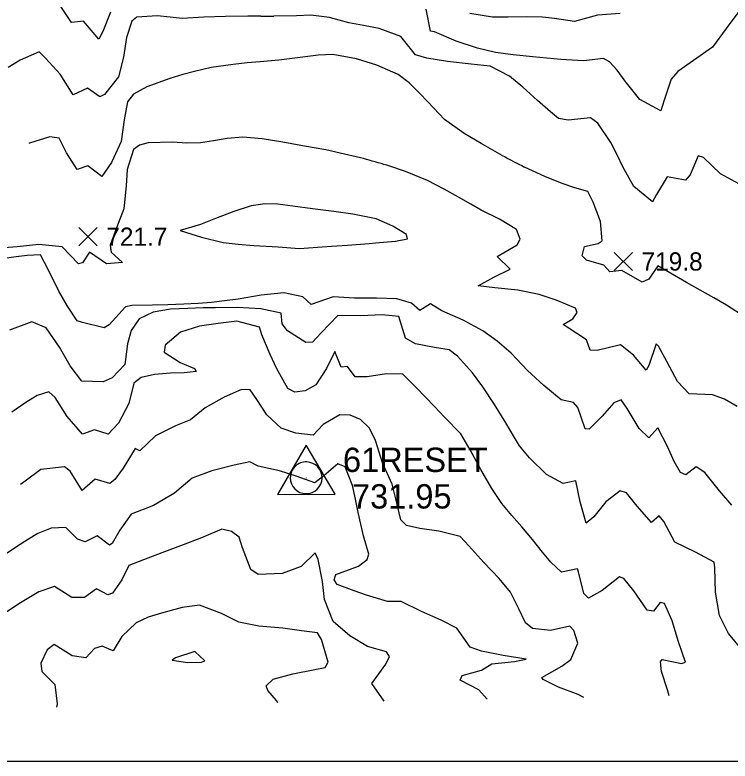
# Model space of a CAD drawing. Extents: x 2566079 to 2571326, y 424054 to 426896.
# Drawn here: x 2568149 to 2568737, y 424077 to 424690 of the extents above; entities that cross this region are included whole.
import ezdxf

# ---------------------------------------------------------------- set-up
doc = ezdxf.new("R2010")
doc.units = 0
for name, color, linetype in [('Contour_ADS_Major', 7, 'Continuous'), ('Contour_ADS_Minor', 7, 'Continuous'), ('Contour_ADS_Spot_Elevation', 7, 'Continuous'), ('Contour_ADS_State_Plane_Border', 7, 'Continuous'), ('Control_Point', 7, 'Continuous')]:
    doc.layers.add(name, color=color, linetype=linetype)

# ---------------------------------------------------------------- blocks, each defined once
blk = doc.blocks.new('S750')
at = {"layer": 'Contour_ADS_Spot_Elevation'}
for p, q in [((-0.5, 0.498), (0.5, -0.498)), ((-0.498, -0.5), (0.498, 0.5))]:
    blk.add_line(p, q, dxfattribs=at)
blk = doc.blocks.new('S803')
at = {"layer": 'Control_Point'}
for q in [(0, 0.002), (0, 0), (0, 0), (0, 0)]:
    blk.add_line((0, 0), q, dxfattribs=at)
blk.add_lwpolyline([(-0.007, 0.677), (-0.597, -0.336), (-0.597, -0.336), (0.587, -0.332), (-0.007, 0.677)], dxfattribs=at)
for centre, radius, start, end in [((-0.005, 0.005), 0.327, 88.1387, 179.8395), ((-0.005, 0.006), 0.326, 269.4188, 88.1799), ((-0.007, 0.005), 0.325, 179.8295, 269.8262)]:
    blk.add_arc(centre, radius, start, end, dxfattribs=at)

msp = doc.modelspace()

# ---------------------------------------------------------------- linework, layer by layer
at = {"layer": 'Contour_ADS_Major'}
for points in [[(2568549.85, 424574.7), (2568532.41, 424584.45), (2568518.5, 424592.66), (2568502.34, 424604.36), (2568488.92, 424618.43), (2568481.63, 424626.16), (2568473.24, 424634.28), (2568464.37, 424641.21), (2568446.92, 424648.81), (2568430.12, 424654), (2568410.76, 424657.7), (2568398.56, 424657.18), (2568385.96, 424655.57), (2568366.39, 424652.86), (2568350.92, 424651.71), (2568340.3, 424650.76), (2568328.74, 424649.55), (2568310.73, 424647.08), (2568297.07, 424643.77), (2568287.47, 424641.09), (2568276.62, 424637.89), (2568257.79, 424631.16), (2568246.75, 424625.15), (2568241.8, 424618.62), (2568239.23, 424604.06), (2568236.83, 424586.07), (2568228.74, 424569.03), (2568220.9, 424557.49), (2568209.37, 424566.13), (2568200.71, 424563.14), (2568191.95, 424576.74), (2568185.68, 424588.91), (2568178.12, 424589.96), (2568161.52, 424584.69), (2568160.91, 424584.43)], [(2568750.24, 424441.21), (2568733.97, 424451.64), (2568723.72, 424457.62), (2568712.4, 424464.13), (2568701.36, 424470.45), (2568686.1, 424479.17), (2568677.62, 424484.07), (2568670.19, 424472.92), (2568664.82, 424470.49), (2568648.2, 424480.12), (2568638.26, 424479.05), (2568633.27, 424484.58), (2568619.12, 424488.7), (2568615.49, 424492.12), (2568617.31, 424499.79), (2568628.71, 424502.41), (2568631.96, 424504.62), (2568630.64, 424520.37), (2568624.62, 424536.32), (2568620.03, 424545.13), (2568609.35, 424548.08), (2568599, 424551.67), (2568584.96, 424557.39), (2568568.16, 424565.18)], [(2568616.82, 424129.4), (2568612.14, 424131.83), (2568596.16, 424137.89), (2568583.52, 424144), (2568582.28, 424145.8), (2568598.74, 424155.21), (2568606.07, 424160.44), (2568612.07, 424173.95), (2568608.68, 424184.45), (2568605.37, 424187.94), (2568589.39, 424184.5), (2568574.82, 424186.09), (2568569.03, 424190.67), (2568563.29, 424202.87), (2568556.49, 424215.77), (2568547.3, 424227.25), (2568534.67, 424240.38), (2568522.25, 424253.84), (2568515.21, 424261.69), (2568497.65, 424266), (2568482.26, 424268.1), (2568471.13, 424270.79), (2568466.52, 424275.36), (2568462.34, 424292.62), (2568459.46, 424304.62), (2568451.37, 424322.26), (2568445.81, 424340.46), (2568440.66, 424350.57), (2568433.37, 424357.72), (2568424.85, 424361.35), (2568416.31, 424361.46), (2568402.82, 424353.62), (2568394.43, 424344.91), (2568380.2, 424346.53), (2568368.26, 424350.55), (2568356.5, 424361.72), (2568348.12, 424374.22), (2568342.62, 424382.08), (2568335.56, 424382.48), (2568321.49, 424376.07), (2568305.75, 424367.22), (2568293.75, 424357.61), (2568281.4, 424352.59), (2568264.93, 424344.41), (2568252, 424331.89), (2568248.18, 424333.83), (2568238.4, 424317.68), (2568231.45, 424308.42), (2568227.38, 424305.11), (2568215.45, 424308.8), (2568204.68, 424299.52), (2568194.83, 424315.18), (2568190.26, 424318.82), (2568170.71, 424316.66), (2568157.85, 424307.01), (2568153.92, 424304.34)]]:
    msp.add_lwpolyline(points, dxfattribs=at)
msp.add_arc((2568812.9, 425058.27), 550.49, 241.45449, 243.60256, dxfattribs=at)
at = {"layer": 'Contour_ADS_Minor'}
for points in [[(2568228.07, 424692.54), (2568221.78, 424676.61), (2568218.51, 424670.3), (2568205.88, 424685.08), (2568195.84, 424683.95), (2568184.98, 424700.31)], [(2568745.04, 424694.1), (2568733.81, 424678.88), (2568722.68, 424663.56), (2568707.04, 424652.77), (2568694.22, 424643.67), (2568688.67, 424637.46), (2568682.95, 424620.04), (2568680.15, 424611.3), (2568662.76, 424620.74), (2568650.7, 424635.71), (2568644.25, 424644.68), (2568638.09, 424651.63), (2568633.03, 424654.4), (2568616.52, 424652.46), (2568598.02, 424653.55), (2568586.41, 424654.62), (2568574.84, 424655.75), (2568558.83, 424657.39), (2568544.29, 424659.29), (2568529.56, 424662.96), (2568512.05, 424668.7), (2568494.25, 424676.22), (2568490.8, 424676.94), (2568487.28, 424694.85)], [(2568646.81, 424691.3), (2568628.19, 424689.96), (2568609.12, 424684.85), (2568592.67, 424687.34), (2568582.88, 424688.32), (2568569.38, 424688.58), (2568554.65, 424688.44), (2568541.83, 424688.36), (2568523.23, 424691.2)], [(2568340.93, 424689.03), (2568322.36, 424688.82), (2568304.72, 424688.24), (2568286.86, 424687.16), (2568277.1, 424688.23), (2568266.19, 424689.39), (2568249.72, 424688.38), (2568245.54, 424685.02), (2568241.12, 424671.52), (2568238.58, 424655.57), (2568234.48, 424639.31), (2568223.08, 424624.87), (2568219.15, 424622.89), (2568209.16, 424630.01), (2568197.33, 424624.54), (2568186.72, 424641.39), (2568174.48, 424654.71), (2568169.3, 424659.72), (2568153.66, 424652.92), (2568143.78, 424646.86)], [(2568744.23, 424551.31), (2568729.27, 424559.69), (2568715.11, 424572.97), (2568710.74, 424574.29), (2568704.2, 424558.89), (2568700.45, 424554.29), (2568685.41, 424557.15), (2568676.44, 424542.58), (2568673.2, 424536.62), (2568658.05, 424549.06), (2568648.94, 424565.23), (2568644.2, 424575.08), (2568639.07, 424585.25), (2568628.39, 424601.35), (2568622.41, 424605.51), (2568604.03, 424603.64), (2568595.99, 424605.13), (2568589.38, 424610.54), (2568578.9, 424619.86), (2568566.69, 424630.71), (2568555.72, 424639.96), (2568539.87, 424648.14), (2568524.39, 424649.8), (2568504.92, 424651.98), (2568487.96, 424654.5), (2568478.69, 424657.46), (2568466.4, 424672.52), (2568448.78, 424679.03), (2568435.96, 424681.43), (2568423.85, 424683.66), (2568407.94, 424687.96), (2568392.5, 424689.86), (2568380.87, 424689.53), (2568362.3, 424689.25)], [(2568433.34, 424572.69), (2568416.77, 424576.7), (2568404.87, 424579.22), (2568395.2, 424580.99), (2568384.22, 424582.96), (2568369.46, 424585.72), (2568352.68, 424588.37), (2568336.73, 424589.63), (2568323.69, 424588.71), (2568312.67, 424586.66), (2568302.05, 424585), (2568290.63, 424584.83), (2568279, 424585.49), (2568259.03, 424585.17), (2568251.85, 424583.11), (2568246.76, 424579.71), (2568241.68, 424563.04), (2568240.97, 424549.71), (2568238.85, 424530.85), (2568233.02, 424515.28), (2568227.66, 424500.96), (2568228.48, 424495.31), (2568237.81, 424486.66), (2568224.7, 424485.62), (2568210.58, 424495.22), (2568204.95, 424486.6), (2568201.63, 424485.58), (2568188.37, 424499.65), (2568169.21, 424501.64), (2568151.31, 424499.51), (2568133.44, 424498.22)], [(2568742.83, 424368.33), (2568732.46, 424374.33), (2568722.54, 424378.13), (2568703.28, 424378.8), (2568693.74, 424389.05), (2568685.08, 424405.49), (2568678.32, 424418.09), (2568676.19, 424419.87), (2568670.25, 424402.25), (2568668.12, 424398.36), (2568657.68, 424410.62), (2568647, 424419.2), (2568627.71, 424414.47), (2568622.13, 424414.67), (2568618.98, 424423.08), (2568603.13, 424433.59), (2568599.83, 424435.92), (2568607.8, 424440.36), (2568611.42, 424445.77), (2568610.14, 424449.28), (2568594.15, 424455.8), (2568580.04, 424460.38), (2568562.51, 424463.9), (2568543.79, 424466.04), (2568530.09, 424467.65), (2568542.96, 424474.64), (2568556.22, 424481.17), (2568545.55, 424491.56), (2568562, 424501.17), (2568564.64, 424505.87), (2568561.64, 424513.78), (2568547.5, 424522.45), (2568532.65, 424529.8), (2568523.93, 424534.65), (2568513.91, 424540.4), (2568502.21, 424547.01), (2568488.35, 424554.05), (2568471.81, 424560.99)], [(2568738.35, 424287.36), (2568728.28, 424299.26), (2568716.25, 424314.2), (2568709.05, 424318.94), (2568700.57, 424312.37), (2568696.27, 424314.24), (2568691.03, 424323.19), (2568685.57, 424335.56), (2568677.55, 424350.85), (2568670.4, 424342.7), (2568662.38, 424350.43), (2568652.34, 424366.87), (2568647.51, 424373.94), (2568641.46, 424371.47), (2568631.98, 424360.61), (2568621.15, 424349.74), (2568618.03, 424349.96), (2568611.93, 424367.59), (2568608.51, 424371.66), (2568598.25, 424373.92), (2568584.04, 424385.66), (2568570.51, 424397.9), (2568557.03, 424412.15), (2568545.54, 424422), (2568533.76, 424430.68), (2568517.69, 424439.42), (2568500.26, 424447.09), (2568490.93, 424452.92), (2568482.17, 424447.41), (2568475.34, 424453.26), (2568463.18, 424456.88), (2568446.59, 424457.35), (2568428.46, 424457.57), (2568410.92, 424458.6), (2568392.88, 424452.24), (2568386.1, 424458.55), (2568370.38, 424461.73), (2568351.81, 424459.79), (2568332.9, 424456.72), (2568321.65, 424455.12), (2568310.82, 424453.92), (2568299.96, 424453.09), (2568288.2, 424452.51), (2568275.18, 424452.07), (2568262.45, 424451.74), (2568245.44, 424451.33), (2568240.34, 424450.34), (2568226.99, 424435.62), (2568222.72, 424432.94), (2568204.97, 424437.51), (2568200.54, 424438.81), (2568192.59, 424450.87), (2568185.5, 424463.12), (2568177.05, 424480.55), (2568170.48, 424492.92), (2568159.43, 424492.49), (2568150.52, 424491.51), (2568138.3, 424489.86)], [(2568746.2, 424169.44), (2568735.8, 424182), (2568728.38, 424196.68), (2568725.02, 424215.85), (2568724.58, 424235.78), (2568724.08, 424240.61), (2568708.55, 424248.88), (2568691.55, 424256.84), (2568682.72, 424273.85), (2568678.78, 424278.58), (2568672.44, 424273.13), (2568660.64, 424286.49), (2568651.88, 424297.56), (2568646.68, 424299.17), (2568635.07, 424290.14), (2568625.05, 424277.82), (2568618.84, 424272.66), (2568613.74, 424289.99), (2568610.24, 424307.41), (2568599.79, 424305.12), (2568586.27, 424312.48), (2568572.33, 424326.24), (2568564.02, 424336.11), (2568559.94, 424342.93), (2568552.74, 424355.04), (2568543.56, 424370.04), (2568533.99, 424384.62), (2568525.4, 424396.1), (2568512.99, 424409.84), (2568506.11, 424414.96), (2568494.23, 424417.01), (2568478.43, 424419.9), (2568470.42, 424424.68), (2568464.81, 424442.41), (2568451.17, 424443.84), (2568433.75, 424442.93), (2568414.79, 424443.25), (2568401.09, 424428.88), (2568393.89, 424421.34), (2568388.53, 424420.96), (2568373.43, 424430.68), (2568369.03, 424436.48), (2568368.31, 424445.01), (2568351.59, 424448.6), (2568332.21, 424449.79), (2568314.1, 424449.61), (2568304.13, 424449.38), (2568291.6, 424449.05), (2568277.17, 424448.34), (2568263, 424445.98), (2568251.62, 424440.41), (2568244.88, 424430.89), (2568241.8, 424419.84), (2568239.83, 424403.02), (2568229.32, 424391.95), (2568221.84, 424388.62), (2568204.48, 424389.3), (2568194.74, 424401.9), (2568186.04, 424417.09), (2568175.2, 424433.18), (2568163.46, 424438), (2568144.99, 424431.12)], [(2568686.86, 424130.67), (2568685.56, 424135.6), (2568680.76, 424150.6), (2568679.76, 424158.65), (2568681.3, 424160.55), (2568697.05, 424157.3), (2568700.35, 424158.29), (2568694.64, 424175.08), (2568689.36, 424192.24), (2568683.09, 424206.53), (2568679.64, 424207.47), (2568674.1, 424200.15), (2568668.82, 424201.14), (2568657.85, 424217.12), (2568649.7, 424227.19), (2568646.07, 424228.43), (2568632.06, 424217.25), (2568620.68, 424210.99), (2568616.88, 424214.89), (2568612.36, 424232.6), (2568611.79, 424235.07), (2568598.41, 424232.32), (2568589.82, 424240.62), (2568583.03, 424248.88), (2568574.64, 424259.08), (2568565.85, 424269.48), (2568557.58, 424278.93), (2568549.56, 424288.78), (2568541.18, 424300.99), (2568532.16, 424316.58), (2568523.35, 424332.78), (2568515.92, 424345.9), (2568502.36, 424359.66), (2568494.13, 424368.42), (2568486.8, 424376.07), (2568478.75, 424384.35), (2568468.15, 424395.09), (2568454.85, 424395.18), (2568438.9, 424392.9), (2568428.97, 424392.88), (2568422.76, 424401.29), (2568417.53, 424400.66), (2568412.41, 424413.71), (2568405.57, 424399.57), (2568396.6, 424386.13), (2568387.92, 424381.33), (2568379.34, 424380.08), (2568373.55, 424383.19), (2568364.75, 424399.38), (2568359.16, 424411.17), (2568352.19, 424427.24), (2568350.44, 424433.65), (2568331.86, 424438.58), (2568316.47, 424436.59), (2568301.06, 424434.42), (2568285.45, 424429.52), (2568272.9, 424418.75), (2568272.19, 424413.01), (2568285.22, 424404.6), (2568297.03, 424399.67), (2568298.48, 424397.12), (2568288.38, 424395.98), (2568277.21, 424395.76), (2568264.24, 424394.79), (2568253.27, 424392.22), (2568247.07, 424387.57), (2568243.07, 424370.82), (2568234.56, 424354.79), (2568226.17, 424345.83), (2568214.91, 424349.34), (2568204.9, 424345.58), (2568192.44, 424360.21), (2568182.39, 424375.94), (2568177.29, 424380.49), (2568167.68, 424377.51), (2568158.45, 424371.71), (2568146.92, 424363.66)], [(2568537.52, 424127.96), (2568530.61, 424135.54), (2568515.23, 424143.67), (2568516.97, 424147.39), (2568532.78, 424151.68), (2568541.27, 424157.03), (2568559.88, 424158.96), (2568569.42, 424160.97), (2568550.52, 424163.86), (2568532.77, 424167.29), (2568523.56, 424170.78), (2568512.5, 424186.34), (2568499.59, 424192.76), (2568483.47, 424199.91), (2568466.91, 424208.33), (2568455.62, 424208.19), (2568438.42, 424213.51), (2568428.12, 424216.87), (2568414.2, 424222.31), (2568411.74, 424225.96), (2568413.02, 424230.44), (2568431.75, 424237.16), (2568438.83, 424242.68), (2568440.26, 424247.12), (2568435.92, 424262.1), (2568431.54, 424281.48), (2568429.3, 424292.32), (2568426.75, 424303.65), (2568420.86, 424318.78), (2568414.84, 424321.44), (2568403.14, 424311.48), (2568395.97, 424305.83), (2568380.58, 424311.29), (2568366.74, 424315.48), (2568349.21, 424319.38), (2568342.51, 424323.03), (2568329.57, 424320.16), (2568311.28, 424315.61), (2568295.06, 424309.51), (2568280.58, 424297.13), (2568263.41, 424287.21), (2568244.84, 424279.9), (2568235.63, 424266.85), (2568229.31, 424255.84), (2568227.18, 424254.58), (2568216.88, 424262.27), (2568207.13, 424257.34), (2568200.76, 424259.33), (2568191.32, 424268.89), (2568179.18, 424268.46), (2568168.19, 424264.08), (2568160.53, 424259.51), (2568150.8, 424253.19), (2568138.92, 424245.29)], [(2568452.71, 424126.42), (2568442.79, 424140.98), (2568454.28, 424156.64), (2568457.17, 424163.13), (2568454.76, 424166.86), (2568439.02, 424171.29), (2568424.5, 424179.97), (2568410.83, 424191.77), (2568403.74, 424209.82), (2568402.17, 424224.69), (2568398.57, 424242.73), (2568396.11, 424248.15), (2568384.63, 424237.01), (2568368.98, 424231.22), (2568349.19, 424230.46), (2568343.35, 424234.53), (2568336.37, 424252.34), (2568333.67, 424260.97), (2568327.5, 424265.76), (2568319.54, 424267.67), (2568302.7, 424260.6), (2568287.63, 424254.84), (2568270.06, 424248.14), (2568255.15, 424242.47), (2568243.03, 424237.69), (2568237.16, 424226.07), (2568229.49, 424215.14), (2568225.74, 424213.67), (2568216.51, 424218.54), (2568206.55, 424211.55), (2568196.17, 424211.42), (2568182, 424220.62), (2568169.15, 424216.11), (2568152.61, 424206.25), (2568141.59, 424198.81)], [(2568365.57, 424124.83), (2568364.34, 424126.83), (2568357.31, 424135.05), (2568355.79, 424138.82), (2568361.52, 424144.35), (2568377.88, 424148.8), (2568395.72, 424152.35), (2568404.26, 424154.12), (2568406.94, 424158.37), (2568401.26, 424176.89), (2568398.18, 424182.48), (2568384.98, 424184.12), (2568369.58, 424186.19), (2568349.74, 424188.06), (2568333.51, 424191.16), (2568319.25, 424198.42), (2568301.06, 424205.17), (2568286.72, 424203.37), (2568269.79, 424198.74), (2568258.86, 424195.28), (2568248.98, 424190.8), (2568237.15, 424179.49), (2568230.11, 424167.72), (2568221.01, 424171.65), (2568214.7, 424169.74), (2568207.78, 424161.92), (2568196.57, 424163.52), (2568181.67, 424172.91), (2568175.92, 424168.57), (2568170.78, 424157.55), (2568171.59, 424150.81), (2568182.12, 424140.08), (2568184.02, 424124.09), (2568183.48, 424121.52)]]:
    msp.add_lwpolyline(points, dxfattribs=at)
for points in [[(2568445.63, 424502.78), (2568462.22, 424504.33), (2568471.86, 424506.06), (2568471.17, 424509.68), (2568459.95, 424516.73), (2568446.28, 424522.74), (2568427.17, 424526.56), (2568411.49, 424528.69), (2568393.87, 424530.95), (2568377.72, 424533.09), (2568365.43, 424534.74), (2568355.07, 424535.08), (2568343.65, 424533.21), (2568329.25, 424528.68), (2568314.18, 424522.96), (2568301.86, 424517.99), (2568285.26, 424513.02), (2568302.61, 424507.68), (2568320.41, 424503.2), (2568332.83, 424501.71), (2568345.83, 424500.76), (2568365.7, 424499.57), (2568383.27, 424498.16), (2568397.93, 424499.3), (2568409.54, 424500.16), (2568422.61, 424501.1), (2568440.51, 424502.35), (2568445.63, 424502.78)], [(2568291.24, 424157.98), (2568302.86, 424158.31), (2568305.56, 424159.42), (2568297.14, 424167.02), (2568281.31, 424161.98), (2568278.61, 424159.97), (2568291.24, 424157.98)]]:
    msp.add_lwpolyline(points, close=True, dxfattribs=at)
for centre, radius, start, end in [((2568566.27, 403309.09), 21381.13, 90.575228, 90.603875), ((2568316.04, 428662.41), 3973.43, 270.5131, 270.66711), ((2568313.29, 424101.96), 485.8, 73.32594, 75.69308), ((2568360.23, 424256.34), 324.44, 69.88414, 73.44375)]:
    msp.add_arc(centre, radius, start, end, dxfattribs=at)
at = {"layer": 'Contour_ADS_State_Plane_Border'}
msp.add_lwpolyline([(2566079.33, 424077.11), (2571302.93, 424077.11), (2571302.93, 426873.74), (2566079.33, 426873.74), (2566079.33, 424077.11)], close=True, dxfattribs=at)

# ---------------------------------------------------------------- block references
at = {"layer": 'Contour_ADS_Spot_Elevation', "xscale": 15, "yscale": 15}
for p in [(2568209.52, 424507.95), (2568649.29, 424487.6)]:
    msp.add_blockref('S750', p, dxfattribs=at)
at = {"layer": 'Control_Point', "xscale": 40, "yscale": 40}
msp.add_blockref('S803', (2568388.97, 424309.62), dxfattribs=at)

# ---------------------------------------------------------------- texts
at = {"layer": 'Contour_ADS_Spot_Elevation'}
for s, p in [('721.7', (2568224.52, 424500.45)), ('719.8', (2568664.29, 424480.1))]:
    msp.add_text(s, height=15, dxfattribs=at).set_placement(p)
at = {"layer": 'Control_Point'}
for s, p in [('61RESET', (2568418.97, 424314.62)), (' 731.95', (2568418.97, 424284.62))]:
    msp.add_text(s, height=20, dxfattribs=at).set_placement(p)

doc.saveas('drawing.dxf')
